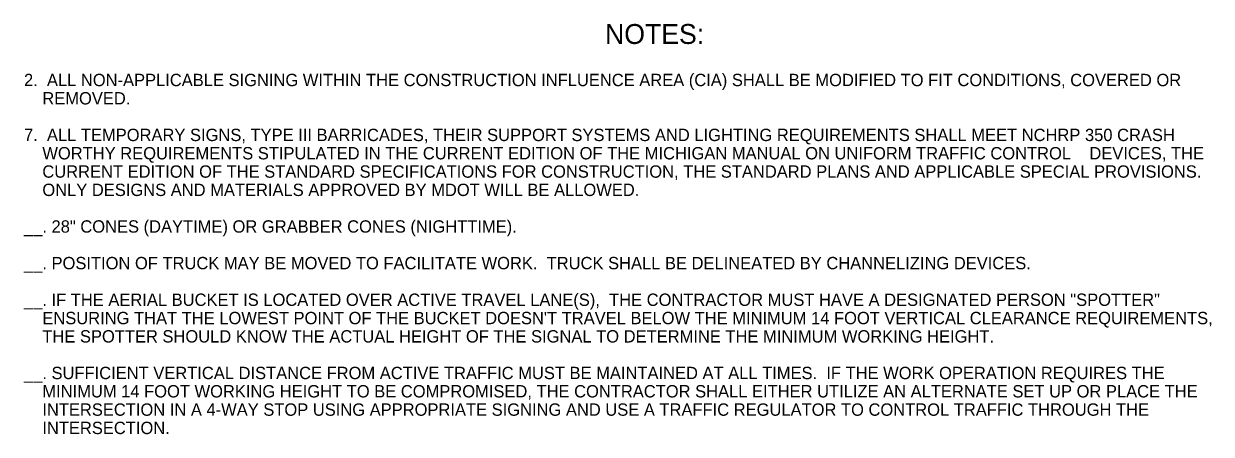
# Model space of a CAD drawing. Extents: x 376 to 2016, y -51 to 984.
# Drawn here: x 1311 to 1907, y 726 to 932 of the extents above; entities that cross this region are included whole.
import ezdxf

# ---------------------------------------------------------------- set-up
doc = ezdxf.new("R2010")
doc.units = 0
doc.layers.add('TYPICAL_TEXT_DIMEN_EX', color=7, linetype='Continuous')

msp = doc.modelspace()

# ---------------------------------------------------------------- texts
at = {"layer": 'TYPICAL_TEXT_DIMEN_EX'}
for s, height, p in [('NOTES:', 10, (1602.58, 922.16)), ('2.  ALL NON-APPLICABLE SIGNING WITHIN THE CONSTRUCTION INFLUENCE AREA (CIA) SHALL BE MODIFIED TO FIT CONDITIONS, COVERED OR', 6.2, (1310.66, 900.96)), ('    REMOVED.', 6.2, (1310.66, 891.76)), ('7.  ALL TEMPORARY SIGNS, TYPE III BARRICADES, THEIR SUPPORT SYSTEMS AND LIGHTING REQUIREMENTS SHALL MEET NCHRP 350 CRASH', 6.2, (1310.66, 873.36)), ('    WORTHY REQUIREMENTS STIPULATED IN THE CURRENT EDITION OF THE MICHIGAN MANUAL ON UNIFORM TRAFFIC CONTROL    DEVICES, THE', 6.2, (1310.66, 864.16)), ('    CURRENT EDITION OF THE STANDARD SPECIFICATIONS FOR CONSTRUCTION, THE STANDARD PLANS AND APPLICABLE SPECIAL PROVISIONS. ', 6.2, (1310.66, 854.96)), ('    ONLY DESIGNS AND MATERIALS APPROVED BY MDOT WILL BE ALLOWED.', 6.2, (1310.66, 845.76))]:
    msp.add_text(s, height=height, dxfattribs=at).set_placement(p)
for s, p in [('__. 28" CONES (DAYTIME) OR GRABBER CONES (NIGHTTIME).', (1310.66, 827.36)), ('__. POSITION OF TRUCK MAY BE MOVED TO FACILITATE WORK.  TRUCK SHALL BE DELINEATED BY CHANNELIZING DEVICES.', (1310.66, 808.96)), ('__. IF THE AERIAL BUCKET IS LOCATED OVER ACTIVE TRAVEL LANE(S),  THE CONTRACTOR MUST HAVE A DESIGNATED PERSON "SPOTTER"', (1310.66, 790.56)), ("    ENSURING THAT THE LOWEST POINT OF THE BUCKET DOESN'T TRAVEL BELOW THE MINIMUM 14 FOOT VERTICAL CLEARANCE REQUIREMENTS,", (1310.66, 781.36)), ('    THE SPOTTER SHOULD KNOW THE ACTUAL HEIGHT OF THE SIGNAL TO DETERMINE THE MINIMUM WORKING HEIGHT.', (1310.66, 772.16)), ('__. SUFFICIENT VERTICAL DISTANCE FROM ACTIVE TRAFFIC MUST BE MAINTAINED AT ALL TIMES.  IF THE WORK OPERATION REQUIRES THE', (1310.66, 753.76)), ('    MINIMUM 14 FOOT WORKING HEIGHT TO BE COMPROMISED, THE CONTRACTOR SHALL EITHER UTILIZE AN ALTERNATE SET UP OR PLACE THE', (1310.66, 744.56)), ('    INTERSECTION IN A 4-WAY STOP USING APPROPRIATE SIGNING AND USE A TRAFFIC REGULATOR TO CONTROL TRAFFIC THROUGH THE', (1310.66, 735.36)), ('    INTERSECTION.', (1310.66, 726.16))]:
    msp.add_text(s, height=6.2, rotation=360, dxfattribs=at).set_placement(p)

doc.saveas('drawing.dxf')
